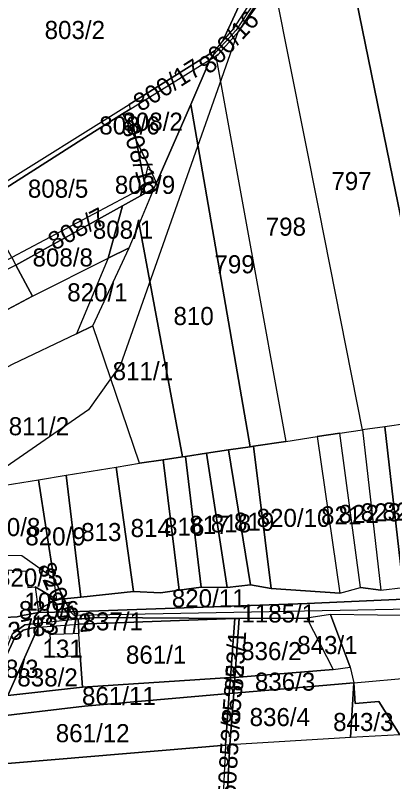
# Model space of a CAD drawing. Extents: x -623250 to -619626, y -1079612 to -1075424.
# Drawn here: x -621247.2 to -621038.1, y -1077337.8 to -1076913.6 of the extents above; entities that cross this region are included whole.
import ezdxf

# ---------------------------------------------------------------- set-up
doc = ezdxf.new("R2010")
doc.units = 0
for name, color, linetype in [('Cestní síť', 7, 'Continuous'), ('Hranice šetřená (k_ú_Džbánov - vnitřní obvod)', 7, 'Continuous'), ('Parcela nároku', 7, 'Continuous'), ('Parcelní číslo', 7, 'Continuous'), ('Vodní toky', 7, 'Continuous')]:
    doc.layers.add(name, color=color, linetype=linetype)

msp = doc.modelspace()

# ---------------------------------------------------------------- linework, layer by layer
at = {"layer": 'Cestní síť'}
msp.add_line((-620860.93, -1077239.33), (-621214.45, -1077245.82), dxfattribs=at)
at = {"layer": 'Hranice šetřená (k_ú_Džbánov - vnitřní obvod)'}
for points in [[(-621265.63, -1077017.55), (-621210.28, -1076982.43), (-621187.76, -1076968.09), (-621182.95, -1076968.95), (-621180.28, -1076982.79), (-621175.85, -1077005.66), (-621175.29, -1077008.58), (-621176.78, -1077009.37), (-621249.17, -1077047.73), (-621246.87, -1077052), (-621237.68, -1077069.07), (-621251.52, -1077076.38), (-621294, -1077098.09)], [(-621191.21, -1077163.66), (-621178.34, -1077161.56), (-621165.23, -1077159.59), (-621154.52, -1077157.99), (-621152.97, -1077157.76), (-621141.25, -1077156.01), (-621129.09, -1077154.19), (-621116.92, -1077228.86), (-621129.77, -1077230.27), (-621144.12, -1077230.17), (-621156.36, -1077231.82), (-621166.67, -1077233.21), (-621181.64, -1077232.5), (-621210.93, -1077235.6), (-621220.15, -1077236.58), (-621216.53, -1077243.73), (-621212.37, -1077247.92), (-621212.23, -1077250.58), (-621125.51, -1077247.43), (-621123.12, -1077247.42), (-621125.51, -1077280.09), (-621126.15, -1077288.82), (-621128.23, -1077317.38)], [(-621268.72, -1077174.87), (-621262.25, -1077175.25), (-621234.38, -1077170.7), (-621219.02, -1077168.19), (-621191.21, -1077163.66)], [(-621128.23, -1077317.38), (-621130.34, -1077357.73), (-621129.24, -1077387.69), (-621130.43, -1077396.55), (-621130.91, -1077400.13), (-621133.03, -1077433.89), (-621133.35, -1077450.57), (-621133.77, -1077471.92), (-621134.06, -1077475.73), (-621136.16, -1077503.29), (-621136.94, -1077513.55), (-621137.93, -1077526.56)]]:
    msp.add_lwpolyline(points, dxfattribs=at)
at = {"layer": 'Parcela nároku'}
for points in [[(-621137.46, -1076935.44), (-621136.45, -1076933.16), (-621132.46, -1076928.18), (-621126.16, -1076920.95), (-621116.71, -1076906.26), (-621078.85, -1076879.4), (-621066.72, -1076868.08), (-621042.72, -1076837.79), (-621038.82, -1076834.98), (-621007.66, -1076812.58), (-620966.87, -1076786.13), (-620966.47, -1076787.42), (-620988.84, -1076802.18), (-621002.96, -1076811.5), (-621006.67, -1076813.95), (-621020.36, -1076823.77), (-621033.06, -1076832.89), (-621041.87, -1076839.21), (-621065.58, -1076869.14), (-621077.55, -1076880.26), (-621103.2, -1076898.67), (-621115.37, -1076907.54), (-621124.9, -1076921.91)], [(-621040.87, -1076839.88), (-621032.81, -1076834.22), (-620999.81, -1077010.33), (-620977.01, -1077132.01), (-620978.48, -1077132.22), (-620998.5, -1077135.06), (-621009.6, -1077136.64), (-621010.77, -1077136.81), (-621038.05, -1077003.98), (-621065.15, -1076871.1)], [(-621065.15, -1076871.1), (-621038.05, -1077003.98), (-621010.77, -1077136.81), (-621016.81, -1077137.67), (-621029.67, -1077139.5), (-621042.47, -1077141.32), (-621054.91, -1077143.09), (-621078.91, -1077021.62), (-621102.95, -1076900.09), (-621076.1, -1076880.89)], [(-621119.89, -1076900.74), (-621132.46, -1076928.18), (-621126.16, -1076920.95), (-621116.71, -1076906.26), (-621078.85, -1076879.4), (-621093.46, -1076881.16), (-621114.13, -1076896.47)], [(-621102.95, -1076900.09), (-621103.2, -1076898.67), (-621115.37, -1076907.54), (-621124.9, -1076921.91), (-621137.46, -1076935.44), (-621139.15, -1076938.15), (-621136.06, -1076936.2), (-621134.72, -1076935.36), (-621123.4, -1076922.33), (-621114.12, -1076908.07)], [(-621078.91, -1077021.62), (-621102.95, -1076900.09), (-621114.12, -1076908.07), (-621123.4, -1076922.33), (-621134.72, -1076935.36), (-621136.06, -1076936.2), (-621116.71, -1077042.91), (-621097.28, -1077149.44), (-621079.85, -1077146.83), (-621067.37, -1077144.95), (-621054.91, -1077143.09)], [(-621136.45, -1076933.16), (-621184.11, -1076962.92), (-621183.61, -1076965.53), (-621139.15, -1076938.15), (-621137.46, -1076935.44)], [(-621187.76, -1076968.09), (-621183.61, -1076965.53), (-621139.15, -1076938.15), (-621149.85, -1076962.93), (-621168.92, -1077006.27), (-621173.53, -1076996.4), (-621180.28, -1076982.79), (-621182.95, -1076968.95)], [(-621116.71, -1077042.91), (-621097.28, -1077149.44), (-621115.3, -1077152.12), (-621117.09, -1077152.39), (-621149.85, -1076962.93), (-621139.15, -1076938.15), (-621136.06, -1076936.2)], [(-621316.13, -1077044.13), (-621289.81, -1077027.14), (-621276.8, -1077019.33), (-621259.89, -1077010.22), (-621184.11, -1076962.92), (-621183.61, -1076965.53), (-621187.76, -1076968.09), (-621210.28, -1076982.43), (-621265.63, -1077017.55), (-621315.29, -1077048.32), (-621317.95, -1077049.84), (-621323.41, -1077053.43), (-621328.79, -1077055.44), (-621331.46, -1077056.09), (-621334.27, -1077056.32)], [(-621178.49, -1077029.24), (-621170.15, -1077009.22), (-621168.92, -1077006.27), (-621149.85, -1076962.93), (-621117.09, -1077152.39), (-621129.09, -1077154.19), (-621141.25, -1077156.01), (-621152.97, -1077157.76), (-621154.52, -1077157.99)], [(-621180.28, -1076982.79), (-621175.85, -1077005.66), (-621175.29, -1077008.58), (-621176.78, -1077009.37), (-621249.17, -1077047.73), (-621265.63, -1077017.55), (-621210.28, -1076982.43), (-621187.76, -1076968.09)], [(-621182.95, -1076968.95), (-621187.76, -1076968.09), (-621180.28, -1076982.79)], [(-621180.28, -1076982.79), (-621173.53, -1076996.4), (-621175.85, -1077005.66)], [(-621176.78, -1077009.37), (-621177.76, -1077013.49), (-621170.15, -1077009.22), (-621168.92, -1077006.27), (-621173.53, -1076996.4), (-621175.85, -1077005.66), (-621175.29, -1077008.58)], [(-621176.78, -1077009.37), (-621249.17, -1077047.73), (-621246.87, -1077052), (-621187.87, -1077019.16), (-621177.76, -1077013.49)], [(-621187.87, -1077019.16), (-621195.75, -1077048.12), (-621184.14, -1077042.32), (-621178.49, -1077029.24), (-621170.15, -1077009.22), (-621177.76, -1077013.49)], [(-621187.87, -1077019.16), (-621246.87, -1077052), (-621237.68, -1077069.07), (-621195.75, -1077048.12)], [(-621184.14, -1077042.32), (-621178.49, -1077029.24), (-621154.52, -1077157.99), (-621165.23, -1077159.59), (-621178.34, -1077161.56), (-621204.16, -1077085.48)], [(-621195.75, -1077048.12), (-621213.24, -1077089.84), (-621204.16, -1077085.48), (-621184.14, -1077042.32)], [(-621251.52, -1077076.38), (-621237.68, -1077069.07), (-621195.75, -1077048.12), (-621213.24, -1077089.84), (-621248.89, -1077106.94), (-621280.89, -1077123.84), (-621283.01, -1077121.21), (-621310.49, -1077133.23), (-621335.24, -1077144.05), (-621334, -1077138.41), (-621331.64, -1077139.45), (-621320.19, -1077112.66), (-621294, -1077098.09)], [(-621298.91, -1077073.21), (-621249.17, -1077047.73), (-621246.87, -1077052), (-621325.45, -1077091.18), (-621319.17, -1077056.56), (-621317.95, -1077049.84), (-621315.29, -1077048.32)], [(-621246.87, -1077052), (-621325.45, -1077091.18), (-621328.14, -1077111.81), (-621329.46, -1077117.82), (-621320.19, -1077112.66), (-621294, -1077098.09), (-621251.52, -1077076.38), (-621237.68, -1077069.07)], [(-621213.24, -1077089.84), (-621248.89, -1077106.94), (-621280.89, -1077123.84), (-621275.26, -1077129.83), (-621268.72, -1077174.87), (-621262.25, -1077175.25), (-621234.38, -1077170.7), (-621219.02, -1077168.19), (-621191.21, -1077163.66), (-621178.34, -1077161.56), (-621204.16, -1077085.48)], [(-621032.37, -1077230.4), (-621042.47, -1077141.32), (-621054.91, -1077143.09), (-621044.66, -1077231.77)], [(-621021.32, -1077231.53), (-621029.67, -1077139.5), (-621042.47, -1077141.32), (-621032.37, -1077230.4)], [(-621055.85, -1077230.4), (-621067.37, -1077144.95), (-621079.85, -1077146.83), (-621067.47, -1077233.41)], [(-621054.91, -1077143.09), (-621044.66, -1077231.77), (-621055.85, -1077230.4), (-621067.37, -1077144.95)], [(-621115.3, -1077152.12), (-621097.28, -1077149.44), (-621079.85, -1077146.83), (-621067.47, -1077233.41), (-621105.4, -1077230.88)], [(-621141.25, -1077156.01), (-621129.09, -1077154.19), (-621116.92, -1077228.86), (-621129.77, -1077230.27)], [(-621129.09, -1077154.19), (-621117.09, -1077152.39), (-621115.3, -1077152.12), (-621105.4, -1077230.88), (-621116.92, -1077228.86)], [(-621154.52, -1077157.99), (-621152.97, -1077157.76), (-621144.12, -1077230.17), (-621156.36, -1077231.82), (-621165.23, -1077159.59)], [(-621152.97, -1077157.76), (-621141.25, -1077156.01), (-621129.77, -1077230.27), (-621144.12, -1077230.17)], [(-621191.21, -1077163.66), (-621178.34, -1077161.56), (-621165.23, -1077159.59), (-621156.36, -1077231.82), (-621166.67, -1077233.21), (-621181.64, -1077232.5)], [(-621219.02, -1077168.19), (-621191.21, -1077163.66), (-621181.64, -1077232.5), (-621210.93, -1077235.6)], [(-621234.38, -1077170.7), (-621225.78, -1077225.43), (-621243.53, -1077212.83), (-621261.46, -1077212.45), (-621262.25, -1077175.25)], [(-621234.38, -1077170.7), (-621219.02, -1077168.19), (-621210.93, -1077235.6), (-621220.15, -1077236.58), (-621225.78, -1077225.43)], [(-621261.46, -1077212.45), (-621261.54, -1077220.29), (-621259.67, -1077220.32), (-621254.27, -1077220.41), (-621241.4, -1077221.33), (-621240.16, -1077230.42), (-621236.21, -1077229.88), (-621224.13, -1077237), (-621225.78, -1077225.43), (-621243.53, -1077212.83)], [(-621254.27, -1077220.41), (-621241.4, -1077221.33), (-621240.16, -1077230.42), (-621236.21, -1077229.88), (-621234.49, -1077242.48), (-621234.26, -1077244.2), (-621243.25, -1077245.92), (-621246.23, -1077246.61), (-621253.36, -1077246.98), (-621253.24, -1077251.28), (-621259.06, -1077251.41), (-621260.68, -1077251.44), (-621261.54, -1077220.29), (-621259.67, -1077220.32)], [(-621225.78, -1077225.43), (-621220.15, -1077236.58), (-621224.13, -1077237)], [(-621224.13, -1077237), (-621236.21, -1077229.88), (-621234.49, -1077242.48)], [(-621166.67, -1077233.21), (-621156.36, -1077231.82), (-621144.12, -1077230.17), (-621129.77, -1077230.27), (-621116.92, -1077228.86), (-621105.4, -1077230.88), (-621067.47, -1077233.41), (-621055.85, -1077230.4), (-621044.66, -1077231.77), (-621032.37, -1077230.4), (-621021.32, -1077231.53), (-621009.82, -1077230.96), (-620997.36, -1077230.34), (-620985.48, -1077229.75), (-620964.79, -1077233.21), (-620962.22, -1077233.64), (-621085.4, -1077239.27), (-621216.53, -1077243.73), (-621220.15, -1077236.58), (-621210.93, -1077235.6), (-621181.64, -1077232.5)], [(-621224.13, -1077237), (-621220.15, -1077236.58), (-621216.53, -1077243.73), (-621234.26, -1077244.2), (-621234.49, -1077242.48)], [(-620995.94, -1077249.72), (-621020.46, -1077245.96), (-621072.57, -1077245.28), (-621061.68, -1077274.39), (-621059.63, -1077283.02), (-620960.48, -1077274.17), (-620961.21, -1077243.43)], [(-621212.37, -1077247.92), (-621202.19, -1077247.02), (-621125.51, -1077247.43), (-621212.23, -1077250.58)], [(-621212.23, -1077250.58), (-621125.51, -1077247.43), (-621127.98, -1077280.25), (-621209.97, -1077285.55), (-621211.16, -1077267.99), (-621211.9, -1077255.8)], [(-621127.98, -1077280.25), (-621125.51, -1077247.43), (-621123.12, -1077247.42), (-621125.51, -1077280.09)], [(-621085.66, -1077247.24), (-621071.14, -1077275.69), (-621125.51, -1077280.09), (-621123.12, -1077247.42)], [(-621061.68, -1077274.39), (-621072.57, -1077245.28), (-621085.66, -1077247.24), (-621071.14, -1077275.69)], [(-621248.65, -1077256), (-621241.85, -1077250.96), (-621233.44, -1077250.14), (-621234.48, -1077252.35), (-621238.42, -1077252.8), (-621242.78, -1077254.01), (-621247.45, -1077257.99), (-621263.08, -1077291.76)], [(-621214.67, -1077268.16), (-621211.16, -1077267.99), (-621209.97, -1077285.55), (-621251.27, -1077290.14), (-621234.48, -1077252.35), (-621212.23, -1077250.58), (-621211.9, -1077255.8), (-621215.39, -1077255.93), (-621220.22, -1077256.12), (-621228.03, -1077256.42), (-621227.94, -1077259.11), (-621228.58, -1077259.16), (-621228.11, -1077268.82), (-621219.54, -1077268.4)], [(-621212.23, -1077250.58), (-621212.37, -1077247.92), (-621233.44, -1077250.14), (-621234.48, -1077252.35)], [(-621242.78, -1077254.01), (-621238.42, -1077252.8), (-621234.48, -1077252.35), (-621251.27, -1077290.14), (-621263.08, -1077291.76), (-621247.45, -1077257.99)], [(-621227.94, -1077259.11), (-621228.58, -1077259.16), (-621228.11, -1077268.82), (-621219.54, -1077268.4), (-621214.67, -1077268.16), (-621211.16, -1077267.99), (-621211.9, -1077255.8), (-621215.39, -1077255.93), (-621220.22, -1077256.12), (-621228.03, -1077256.42)], [(-621126.15, -1077288.82), (-621125.51, -1077280.09), (-621071.14, -1077275.69), (-621061.68, -1077274.39), (-621059.63, -1077283.02)], [(-620960.48, -1077274.17), (-620957.12, -1077305.77), (-620974.2, -1077305.88), (-620976.64, -1077305.9), (-621034.08, -1077311.92), (-621045.83, -1077293.38), (-621058.93, -1077294.62), (-621059.63, -1077283.02)], [(-621251.27, -1077290.14), (-621209.97, -1077285.55), (-621127.98, -1077280.25), (-621128.64, -1077289.04), (-621208.91, -1077296.04), (-621261.94, -1077302.25), (-621263.08, -1077291.76)], [(-621127.98, -1077280.25), (-621125.51, -1077280.09), (-621126.15, -1077288.82), (-621128.64, -1077289.04)], [(-621126.15, -1077288.82), (-621059.63, -1077283.02), (-621061.52, -1077313.33), (-621128.23, -1077317.38)], [(-621058.93, -1077294.62), (-621045.83, -1077293.38), (-621034.08, -1077311.92), (-621061.52, -1077313.33), (-621059.63, -1077283.02)], [(-621261.94, -1077302.25), (-621208.91, -1077296.04), (-621128.64, -1077289.04), (-621130.79, -1077317.53), (-621282.39, -1077330.34), (-621263.08, -1077291.76)], [(-621130.79, -1077317.53), (-621128.64, -1077289.04), (-621126.15, -1077288.82), (-621128.23, -1077317.38)], [(-620914.47, -1077367.93), (-620943.73, -1077339.72), (-620976.64, -1077305.9), (-621034.08, -1077311.92), (-621061.52, -1077313.33), (-621128.23, -1077317.38), (-621130.34, -1077357.73), (-621129.24, -1077387.69), (-620989.35, -1077373.8)], [(-621323.27, -1077335.09), (-621282.39, -1077330.34), (-621130.79, -1077317.53), (-621132.51, -1077357.74), (-621240.85, -1077364.46), (-621349.12, -1077371.13), (-621353.6, -1077335.7)], [(-621130.79, -1077317.53), (-621132.51, -1077357.74), (-621130.34, -1077357.73), (-621128.23, -1077317.38)]]:
    msp.add_lwpolyline(points, close=True, dxfattribs=at)
for points in [[(-621261.07, -1076912.95), (-621276.85, -1076943.57), (-621285.83, -1076961.08), (-621293.09, -1076974.77), (-621297.99, -1076984.39), (-621290.77, -1076996.21), (-621278.41, -1077016.7), (-621276.8, -1077019.33), (-621259.89, -1077010.22), (-621184.11, -1076962.92), (-621136.45, -1076933.16), (-621132.46, -1076928.18), (-621119.89, -1076900.74)], [(-621253.36, -1077246.98), (-621246.23, -1077246.61), (-621243.25, -1077245.92), (-621234.26, -1077244.2), (-621216.53, -1077243.73), (-621085.4, -1077239.27), (-620962.22, -1077233.64)], [(-621020.46, -1077245.96), (-621072.57, -1077245.28), (-621085.66, -1077247.24), (-621123.12, -1077247.42), (-621125.51, -1077247.43), (-621202.19, -1077247.02), (-621212.37, -1077247.92), (-621233.44, -1077250.14), (-621241.85, -1077250.96), (-621248.65, -1077256)]]:
    msp.add_lwpolyline(points, dxfattribs=at)
at = {"layer": 'Vodní toky'}
for p, q in [((-621103.97, -1076895.16), (-621123.9, -1076922.96)), ((-621123.9, -1076922.96), (-621188.94, -1077107.07)), ((-621188.94, -1077107.07), (-621206.59, -1077131.92)), ((-621206.59, -1077131.92), (-621268.72, -1077174.87))]:
    msp.add_line(p, q, dxfattribs=at)

# ---------------------------------------------------------------- texts
at = {"layer": 'Parcelní číslo'}
for s, rotation, p in [('800/16', 46.8767, (-621139.35, -1076946.76)), ('800/17', 32.1013, (-621177.73, -1076967.32)), ('808/10', 286.5197, (-621188.42, -1076974.71)), ('808/7', 27.9334, (-621225.56, -1077044.02)), ('820/5', 292.3134, (-621235.13, -1077218.89)), ('837/3', 12.0929, (-621257.17, -1077261.51)), ('837/2', 5.392, (-621237.58, -1077257.52)), ('853/1', 86.6336, (-621121.18, -1077288.07)), ('853/2', 85.5284, (-621122.97, -1077306.65)), ('853/3', 86.5318, (-621124.37, -1077331.04)), ('850', 88.172, (-621125.18, -1077354.22))]:
    msp.add_text(s, height=10, rotation=rotation, dxfattribs=at).set_placement(p)
for s, p in [('803/2', (-621230.93, -1076926.73)), ('808/2', (-621187.84, -1076977.5)), ('808/6', (-621200.62, -1076979.57)), ('797', (-621072.08, -1077010.37)), ('808/5', (-621240.21, -1077014.57)), ('808/9', (-621192.04, -1077012.47)), ('808/1', (-621204.23, -1077037.28)), ('798', (-621108.44, -1077035.62)), ('808/8', (-621237.63, -1077052.64)), ('799', (-621136.83, -1077056.42)), ('820/1', (-621218.41, -1077071.95)), ('810', (-621159.54, -1077085.06)), ('811/1', (-621193.25, -1077115.58)), ('811/2', (-621250.82, -1077146.08)), ('823', (-621055.79, -1077193.76)), ('824', (-621043.77, -1077193.27)), ('820/10', (-621113.48, -1077196.8)), ('821', (-621077.77, -1077195.39)), ('822', (-621068.07, -1077194.63)), ('820/8', (-621266.76, -1077201.88)), ('814', (-621183.29, -1077202.42)), ('816', (-621164.75, -1077201.67)), ('817', (-621150.77, -1077200.66)), ('818', (-621138.87, -1077199.8)), ('819', (-621126, -1077198.94)), ('820/9', (-621241.64, -1077207.05)), ('813', (-621210.7, -1077204.64)), ('820/3', (-621257.29, -1077229.79)), ('820/11', (-621160.46, -1077241.3)), ('100', (-621242.12, -1077243.16)), ('820/6', (-621245.2, -1077247.85)), ('1185/1', (-621121.9, -1077249.71)), ('837/1', (-621209.9, -1077254.07)), ('131', (-621232.13, -1077269.2)), ('836/2', (-621122.06, -1077270.55)), ('843/1', (-621090.99, -1077267.15)), ('861/1', (-621185.89, -1077272.52)), ('838/3', (-621267.73, -1077280.3)), ('838/2', (-621246.04, -1077285.11)), ('836/3', (-621114.46, -1077287.45)), ('861/11', (-621210.23, -1077295.36)), ('836/4', (-621117.36, -1077307.05)), ('843/3', (-621071.1, -1077309.78)), ('861/12', (-621224.76, -1077315.96))]:
    msp.add_text(s, height=10, dxfattribs=at).set_placement(p)

doc.saveas('drawing.dxf')
